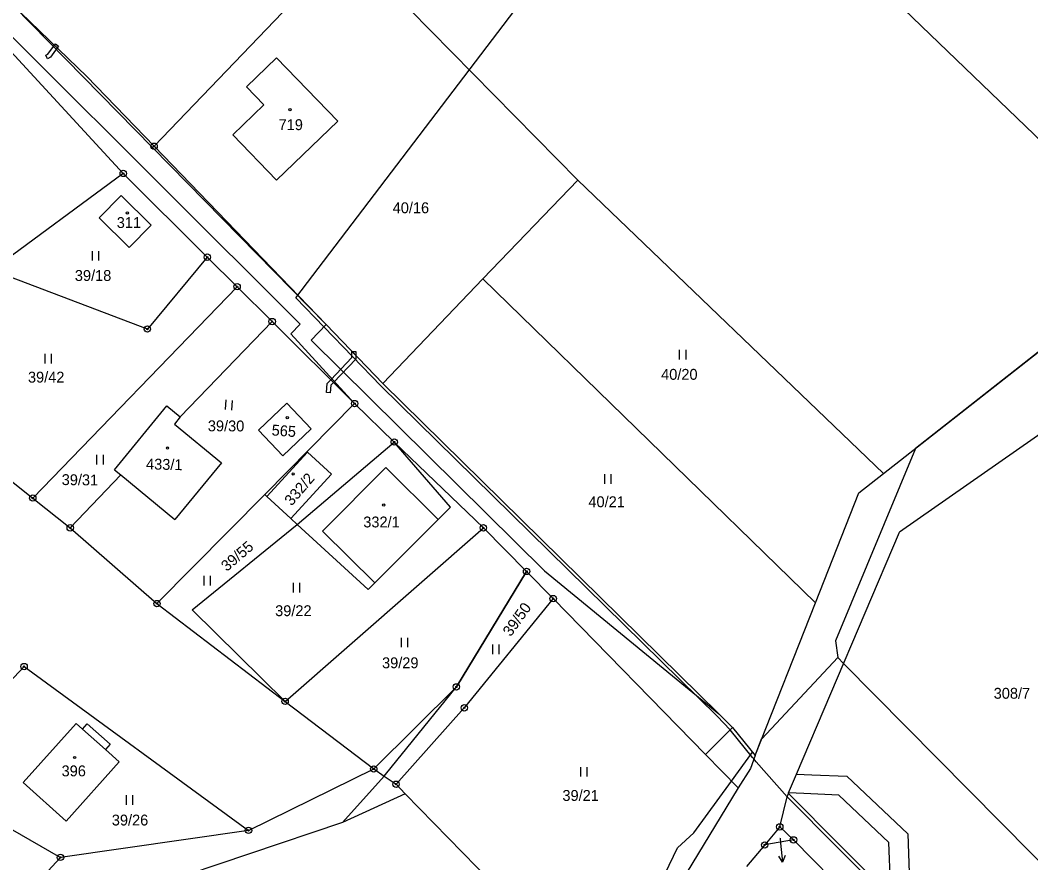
# Model space of a CAD drawing. Extents: x -445050 to -440454, y -1134563 to -1129741.
# Drawn here: x -442715.2 to -442557.4, y -1130802.1 to -1130670.5 of the extents above; entities that cross this region are included whole.
import ezdxf

# ---------------------------------------------------------------- set-up
doc = ezdxf.new("R2010")
doc.units = 0
for name, color, linetype in [('Vrstva 1', 7, 'Continuous'), ('Vrstva 16', 7, 'Continuous'), ('Vrstva 18', 7, 'Continuous'), ('Vrstva 19', 7, 'Continuous'), ('Vrstva 24', 7, 'Continuous'), ('Vrstva 25', 7, 'Continuous'), ('Vrstva 3', 7, 'Continuous'), ('Vrstva 30', 7, 'Continuous'), ('Vrstva 37', 7, 'Continuous'), ('Vrstva 4', 7, 'Continuous'), ('Vrstva 5', 7, 'Continuous'), ('Vrstva 52', 7, 'Continuous'), ('Vrstva 6', 7, 'Continuous')]:
    doc.layers.add(name, color=color, linetype=linetype)

msp = doc.modelspace()

# ---------------------------------------------------------------- linework, layer by layer
at = {"layer": 'Vrstva 1'}
for p, q in [((-442704.75, -1130679.31), (-442715.08, -1130669.35)), ((-442675.13, -1130676.37), (-442679.84, -1130680.93)), ((-442665.58, -1130686.25), (-442675.13, -1130676.37)), ((-442679.84, -1130680.93), (-442677.14, -1130683.73)), ((-442677.14, -1130683.73), (-442681.99, -1130688.4)), ((-442675.16, -1130695.49), (-442665.58, -1130686.25)), ((-442681.99, -1130688.4), (-442675.16, -1130695.49))]:
    msp.add_line(p, q, dxfattribs=at)
for points in [[(-442664.18, -1130658.76), (-442694.26, -1130690.19)], [(-442664.18, -1130658.76), (-442628.11, -1130695.47)], [(-442719.7, -1130672.12), (-442699.07, -1130694.44)], [(-442704.75, -1130679.31), (-442694.26, -1130690.19)], [(-442694.26, -1130690.19), (-442667.41, -1130718.05)], [(-442699.07, -1130694.44), (-442719.59, -1130709.52)], [(-442685.95, -1130707.52), (-442699.07, -1130694.44)], [(-442642.91, -1130710.91), (-442628.11, -1130695.47)], [(-442702.84, -1130701.37), (-442699.4, -1130697.88)], [(-442699.4, -1130697.88), (-442694.7, -1130702.52)], [(-442698.15, -1130706), (-442702.84, -1130701.37)], [(-442694.7, -1130702.52), (-442698.15, -1130706)], [(-442685.95, -1130707.52), (-442695.31, -1130718.74)], [(-442681.3, -1130712.13), (-442685.95, -1130707.52)], [(-442695.31, -1130718.74), (-442719.59, -1130709.52)], [(-442681.3, -1130712.13), (-442713.2, -1130745.14)], [(-442681.3, -1130712.13), (-442675.83, -1130717.57)], [(-442658.56, -1130727.23), (-442642.91, -1130710.91)], [(-442675.83, -1130717.57), (-442690.17, -1130732.48)], [(-442675.83, -1130717.57), (-442662.95, -1130730.38)], [(-442667.41, -1130718.05), (-442658.56, -1130727.23)], [(-442580.36, -1130741.3), (-442555.52, -1130721.77)], [(-442658.56, -1130727.23), (-442606.08, -1130778.83)], [(-442732.98, -1130729.42), (-442713.2, -1130745.14)], [(-442700.44, -1130740.73), (-442692.26, -1130730.76)], [(-442692.26, -1130730.76), (-442690.17, -1130732.48)], [(-442677.96, -1130734.56), (-442673.55, -1130730.34)], [(-442676.99, -1130744.59), (-442662.95, -1130730.38)], [(-442673.55, -1130730.34), (-442669.76, -1130734.32)], [(-442662.95, -1130730.38), (-442656.76, -1130736.39)], [(-442690.17, -1130732.48), (-442691.09, -1130733.59)], [(-442551.85, -1130732.3), (-442577.91, -1130750.47)], [(-442691.09, -1130733.59), (-442683.71, -1130739.65)], [(-442669.76, -1130734.32), (-442674.17, -1130738.54)], [(-442674.17, -1130738.54), (-442677.96, -1130734.56)], [(-442671.91, -1130749.25), (-442656.76, -1130736.39)], [(-442642.85, -1130749.79), (-442656.76, -1130736.39)], [(-442648, -1130746.55), (-442656.76, -1130736.39)], [(-442700.44, -1130740.73), (-442699.45, -1130741.54)], [(-442683.71, -1130739.65), (-442691.01, -1130748.48)], [(-442699.45, -1130741.54), (-442707.35, -1130749.79)], [(-442699.45, -1130741.54), (-442691.01, -1130748.48)], [(-442584.21, -1130744.32), (-442580.36, -1130741.3)], [(-442713.2, -1130745.14), (-442707.35, -1130749.79)], [(-442693.81, -1130761.63), (-442676.99, -1130744.59)], [(-442676.99, -1130744.59), (-442676.67, -1130744.88)], [(-442676.67, -1130744.88), (-442672.91, -1130748.33)], [(-442591, -1130761.49), (-442584.21, -1130744.32)], [(-442648, -1130746.55), (-442649.93, -1130748.49)], [(-442672.91, -1130748.33), (-442671.91, -1130749.25)], [(-442649.93, -1130748.49), (-442659.81, -1130758.41)], [(-442707.35, -1130749.79), (-442693.81, -1130761.63)], [(-442688.33, -1130762.58), (-442671.91, -1130749.25)], [(-442673.81, -1130776.9), (-442642.85, -1130749.79)], [(-442671.91, -1130749.25), (-442660.83, -1130759.44)], [(-442642.85, -1130749.79), (-442636.1, -1130756.6)], [(-442593.94, -1130788.25), (-442577.91, -1130750.47)], [(-442636.1, -1130756.6), (-442647.07, -1130774.64)], [(-442636.1, -1130756.6), (-442631.95, -1130760.85)], [(-442659.81, -1130758.41), (-442660.83, -1130759.44)], [(-442631.95, -1130760.85), (-442645.83, -1130777.91)], [(-442631.95, -1130760.85), (-442608.19, -1130785.18)], [(-442693.81, -1130761.63), (-442673.81, -1130776.9)], [(-442688.33, -1130762.58), (-442673.81, -1130776.9)], [(-442600.44, -1130785.36), (-442591, -1130761.49)], [(-442714.55, -1130771.46), (-442730.78, -1130788.7)], [(-442714.55, -1130771.46), (-442679.52, -1130797.05)], [(-442659.97, -1130787.46), (-442647.07, -1130774.64)], [(-442673.81, -1130776.9), (-442659.97, -1130787.46)], [(-442645.83, -1130777.91), (-442656.49, -1130789.84)], [(-442606.08, -1130778.83), (-442603.98, -1130780.97)], [(-442714.68, -1130789.58), (-442706.4, -1130780.35)], [(-442706.4, -1130780.35), (-442705.43, -1130781.22)], [(-442705.43, -1130781.22), (-442704.7, -1130780.4)], [(-442704.7, -1130780.4), (-442701.12, -1130783.6)], [(-442603.98, -1130780.97), (-442600.44, -1130785.36)], [(-442701.12, -1130783.6), (-442701.86, -1130784.42)], [(-442701.86, -1130784.42), (-442699.7, -1130786.36)], [(-442699.7, -1130786.36), (-442707.98, -1130795.59)], [(-442608.19, -1130785.18), (-442603.08, -1130790.41)], [(-442600.44, -1130785.36), (-442601.15, -1130787.39)], [(-442679.52, -1130797.05), (-442659.97, -1130787.46)], [(-442659.97, -1130787.46), (-442658.35, -1130788.57)], [(-442601.15, -1130787.39), (-442603.08, -1130790.41)], [(-442730.78, -1130788.7), (-442708.87, -1130801.27)], [(-442707.98, -1130795.59), (-442714.68, -1130789.58)], [(-442658.35, -1130788.57), (-442656.49, -1130789.84)], [(-442595.19, -1130791.2), (-442593.94, -1130788.25)], [(-442656.49, -1130789.84), (-442655.04, -1130791.32)], [(-442603.08, -1130790.41), (-442621.06, -1130820.09)], [(-442595.24, -1130791.31), (-442595.19, -1130791.2)], [(-442655.04, -1130791.32), (-442664.85, -1130795.84)], [(-442655.04, -1130791.32), (-442628.23, -1130818.86)], [(-442596.58, -1130796.51), (-442595.44, -1130791.82)], [(-442595.44, -1130791.82), (-442595.24, -1130791.31)], [(-442595.24, -1130791.31), (-442579.23, -1130807.39)], [(-442664.85, -1130795.84), (-442708.39, -1130810.49)], [(-442679.52, -1130797.05), (-442708.87, -1130801.27)], [(-442596.58, -1130796.51), (-442598.93, -1130799.33)], [(-442596.58, -1130796.51), (-442594.43, -1130798.54)], [(-442594.43, -1130798.54), (-442598.93, -1130799.33)], [(-442594.43, -1130798.54), (-442567.43, -1130826.02)], [(-442598.93, -1130799.33), (-442601.75, -1130802.71)], [(-442713.44, -1130806.24), (-442708.87, -1130801.27)]]:
    msp.add_lwpolyline(points, dxfattribs=at)
at = {"layer": 'Vrstva 16'}
msp.add_line((-442596.45, -1130799.04), (-442596.13, -1130802.02), dxfattribs=at)
for points in [[(-442596.53, -1130798.29), (-442596.45, -1130799.04)], [(-442595.74, -1130800.97), (-442596.13, -1130802.02), (-442596.73, -1130801.08)]]:
    msp.add_lwpolyline(points, dxfattribs=at)
at = {"layer": 'Vrstva 24'}
for centre, radius in [((-442694.26, -1130690.19), 0.5), ((-442694.26, -1130690.19), 0.1), ((-442699.07, -1130694.44), 0.5), ((-442699.07, -1130694.44), 0.1), ((-442685.95, -1130707.52), 0.5), ((-442685.95, -1130707.52), 0.1), ((-442681.3, -1130712.13), 0.5), ((-442681.3, -1130712.13), 0.1), ((-442675.83, -1130717.57), 0.5), ((-442695.31, -1130718.74), 0.5), ((-442695.31, -1130718.74), 0.1), ((-442675.83, -1130717.57), 0.1), ((-442662.95, -1130730.38), 0.5), ((-442662.95, -1130730.38), 0.1), ((-442656.76, -1130736.39), 0.5), ((-442656.76, -1130736.39), 0.1), ((-442713.2, -1130745.14), 0.5), ((-442713.2, -1130745.14), 0.1), ((-442707.35, -1130749.79), 0.5), ((-442707.35, -1130749.79), 0.1), ((-442642.85, -1130749.79), 0.5), ((-442642.85, -1130749.79), 0.1), ((-442636.1, -1130756.6), 0.5), ((-442636.1, -1130756.6), 0.1), ((-442693.81, -1130761.63), 0.5), ((-442631.95, -1130760.85), 0.5), ((-442631.95, -1130760.85), 0.1), ((-442693.81, -1130761.63), 0.1), ((-442714.55, -1130771.46), 0.5), ((-442714.55, -1130771.46), 0.1), ((-442647.07, -1130774.64), 0.5), ((-442647.07, -1130774.64), 0.1), ((-442673.81, -1130776.9), 0.5), ((-442673.81, -1130776.9), 0.1), ((-442645.83, -1130777.91), 0.5), ((-442645.83, -1130777.91), 0.1), ((-442659.97, -1130787.46), 0.5), ((-442659.97, -1130787.46), 0.1), ((-442656.49, -1130789.84), 0.5), ((-442656.49, -1130789.84), 0.1), ((-442679.52, -1130797.05), 0.5), ((-442679.52, -1130797.05), 0.1), ((-442596.58, -1130796.51), 0.5), ((-442596.58, -1130796.51), 0.1), ((-442598.93, -1130799.33), 0.5), ((-442594.43, -1130798.54), 0.5), ((-442594.43, -1130798.54), 0.1), ((-442598.93, -1130799.33), 0.1), ((-442708.87, -1130801.27), 0.5), ((-442708.87, -1130801.27), 0.1)]:
    msp.add_circle(centre, radius, dxfattribs=at)
at = {"layer": 'Vrstva 25'}
for p, q in [((-442703.89, -1130708.06), (-442703.89, -1130706.56)), ((-442702.89, -1130708.06), (-442702.89, -1130706.56)), ((-442711.26, -1130724.13), (-442711.26, -1130722.63)), ((-442710.26, -1130724.13), (-442710.26, -1130722.63)), ((-442612.21, -1130723.51), (-442612.21, -1130722.01)), ((-442611.21, -1130723.51), (-442611.21, -1130722.01)), ((-442683.12, -1130731.31), (-442683.01, -1130729.82)), ((-442682.12, -1130731.39), (-442682.01, -1130729.89)), ((-442703.18, -1130739.88), (-442703.18, -1130738.38)), ((-442702.18, -1130739.88), (-442702.18, -1130738.38)), ((-442623.9, -1130742.9), (-442623.9, -1130741.4)), ((-442622.9, -1130742.9), (-442622.9, -1130741.4)), ((-442686.46, -1130758.78), (-442686.46, -1130757.28)), ((-442685.46, -1130758.78), (-442685.46, -1130757.28)), ((-442672.48, -1130759.91), (-442672.48, -1130758.41)), ((-442671.48, -1130759.91), (-442671.48, -1130758.41)), ((-442655.62, -1130768.45), (-442655.62, -1130766.95)), ((-442654.62, -1130768.45), (-442654.62, -1130766.95)), ((-442641.37, -1130769.53), (-442641.37, -1130768.03)), ((-442640.37, -1130769.53), (-442640.37, -1130768.03)), ((-442627.64, -1130788.66), (-442627.64, -1130787.16)), ((-442626.64, -1130788.66), (-442626.64, -1130787.16)), ((-442698.59, -1130793.05), (-442698.59, -1130791.55)), ((-442697.59, -1130793.05), (-442697.59, -1130791.55))]:
    msp.add_line(p, q, dxfattribs=at)
for centre in [(-442673.05, -1130684.47), (-442698.43, -1130700.6), (-442673.46, -1130732.59), (-442692.17, -1130737.34), (-442672.54, -1130741.38), (-442658.41, -1130746.23), (-442706.66, -1130785.67)]:
    msp.add_circle(centre, 0.175, dxfattribs=at)
at = {"layer": 'Vrstva 3'}
for points in [[(-442675.13, -1130676.37), (-442679.84, -1130680.93)], [(-442665.58, -1130686.25), (-442675.13, -1130676.37)], [(-442679.84, -1130680.93), (-442677.14, -1130683.73)], [(-442677.14, -1130683.73), (-442681.99, -1130688.4)], [(-442675.16, -1130695.49), (-442665.58, -1130686.25)], [(-442681.99, -1130688.4), (-442675.16, -1130695.49)], [(-442702.84, -1130701.37), (-442699.4, -1130697.88)], [(-442699.4, -1130697.88), (-442694.7, -1130702.52)], [(-442698.15, -1130706), (-442702.84, -1130701.37)], [(-442694.7, -1130702.52), (-442698.15, -1130706)], [(-442700.44, -1130740.73), (-442692.26, -1130730.76)], [(-442692.26, -1130730.76), (-442690.17, -1130732.48)], [(-442677.96, -1130734.56), (-442673.55, -1130730.34)], [(-442673.55, -1130730.34), (-442669.76, -1130734.32)], [(-442690.17, -1130732.48), (-442691.09, -1130733.59)], [(-442691.09, -1130733.59), (-442683.71, -1130739.65)], [(-442669.76, -1130734.32), (-442674.17, -1130738.54)], [(-442674.17, -1130738.54), (-442677.96, -1130734.56)], [(-442670.32, -1130737.96), (-442676.67, -1130744.88)], [(-442666.56, -1130741.41), (-442670.32, -1130737.96)], [(-442700.44, -1130740.73), (-442699.45, -1130741.54)], [(-442683.71, -1130739.65), (-442691.01, -1130748.48)], [(-442667.96, -1130750.29), (-442658.08, -1130740.37)], [(-442658.08, -1130740.37), (-442649.93, -1130748.49)], [(-442699.45, -1130741.54), (-442691.01, -1130748.48)], [(-442672.91, -1130748.33), (-442666.56, -1130741.41)], [(-442676.67, -1130744.88), (-442672.91, -1130748.33)], [(-442649.93, -1130748.49), (-442659.81, -1130758.41)], [(-442659.81, -1130758.41), (-442667.96, -1130750.29)], [(-442714.68, -1130789.58), (-442706.4, -1130780.35)], [(-442706.4, -1130780.35), (-442705.43, -1130781.22)], [(-442705.43, -1130781.22), (-442701.86, -1130784.42)], [(-442701.86, -1130784.42), (-442699.7, -1130786.36)], [(-442699.7, -1130786.36), (-442707.98, -1130795.59)], [(-442707.98, -1130795.59), (-442714.68, -1130789.58)]]:
    msp.add_lwpolyline(points, dxfattribs=at)
at = {"layer": 'Vrstva 30'}
for points in [[(-442735.26, -1130652.59), (-442716.14, -1130668.32), (-442667.41, -1130718.05), (-442669.73, -1130720.49), (-442633.32, -1130756.52), (-442606.08, -1130778.83), (-442603.98, -1130780.97), (-442608.19, -1130785.18), (-442631.95, -1130760.85), (-442645.83, -1130777.91), (-442656.49, -1130789.84), (-442655.04, -1130791.32), (-442664.85, -1130795.84), (-442658.35, -1130788.57), (-442658.14, -1130788.34), (-442647.07, -1130774.64), (-442636.1, -1130756.6), (-442642.85, -1130749.79), (-442656.76, -1130736.39), (-442662.95, -1130730.38), (-442672.92, -1130719.48), (-442671.46, -1130717.96), (-442736.07, -1130653.46), (-442735.26, -1130652.59)], [(-442709.82, -1130674.42), (-442709.39, -1130674.84), (-442710.43, -1130676.29), (-442710.89, -1130676.51), (-442711.15, -1130675.97), (-442710.83, -1130675.81), (-442709.82, -1130674.42)], [(-442709.82, -1130674.42), (-442709.66, -1130674.19), (-442709.18, -1130674.55), (-442709.39, -1130674.84), (-442709.82, -1130674.42)], [(-442666.68, -1130726.68), (-442663.38, -1130723.21), (-442663.38, -1130722.24), (-442662.78, -1130722.85), (-442662.78, -1130723.45), (-442666.25, -1130727.1), (-442666.68, -1130726.68)], [(-442662.78, -1130722.23), (-442662.78, -1130722.85), (-442663.38, -1130722.24), (-442662.78, -1130722.23)], [(-442666.76, -1130728.71), (-442667.36, -1130728.65), (-442667.24, -1130727.27), (-442666.68, -1130726.68), (-442666.25, -1130727.1), (-442666.66, -1130727.53), (-442666.76, -1130728.71)], [(-442595.19, -1130791.2), (-442593.94, -1130788.25), (-442591.57, -1130788.35), (-442586.13, -1130788.58), (-442576.57, -1130797.6), (-442576.3, -1130805.27), (-442576.12, -1130810.52), (-442579.23, -1130807.39), (-442579.3, -1130805.38), (-442579.53, -1130798.94), (-442587.37, -1130791.53), (-442592.81, -1130791.3), (-442595.19, -1130791.2)]]:
    msp.add_lwpolyline(points, dxfattribs=at)
at = {"layer": 'Vrstva 37'}
for centre in [(-442673.05, -1130684.47), (-442698.43, -1130700.6), (-442673.46, -1130732.59), (-442692.17, -1130737.34), (-442672.54, -1130741.38), (-442658.41, -1130746.23), (-442706.66, -1130785.67)]:
    msp.add_circle(centre, 0.175, dxfattribs=at)
at = {"layer": 'Vrstva 4'}
for points in [[(-442670.32, -1130737.96), (-442676.67, -1130744.88)], [(-442666.56, -1130741.41), (-442670.32, -1130737.96)], [(-442667.96, -1130750.29), (-442658.08, -1130740.37)], [(-442658.08, -1130740.37), (-442649.93, -1130748.49)], [(-442672.91, -1130748.33), (-442666.56, -1130741.41)], [(-442659.81, -1130758.41), (-442667.96, -1130750.29)], [(-442705.43, -1130781.22), (-442701.86, -1130784.42)]]:
    msp.add_lwpolyline(points, dxfattribs=at)
at = {"layer": 'Vrstva 5'}
for points in [[(-442672.12, -1130713.86), (-442551.14, -1130554.82)], [(-442672.12, -1130713.86), (-442658.85, -1130727.63)], [(-442606.37, -1130779.23), (-442658.85, -1130727.63)], [(-442604.34, -1130781.33), (-442606.37, -1130779.23)], [(-442600.83, -1130785.67), (-442604.34, -1130781.33)], [(-442600.63, -1130785.9), (-442600.83, -1130785.67)], [(-442600.25, -1130786.33), (-442600.63, -1130785.9)], [(-442595.44, -1130791.82), (-442600.25, -1130786.33)], [(-442579.58, -1130807.74), (-442595.44, -1130791.82)]]:
    msp.add_lwpolyline(points, dxfattribs=at)
at = {"layer": 'Vrstva 52'}
for points in [[(-442551.46, -1130554.43), (-442549.35, -1130557), (-442548.67, -1130556.55), (-442520.3, -1130583.3), (-442524.35, -1130587.57), (-442518.74, -1130594.43), (-442495.48, -1130622.9), (-442490.57, -1130628.93), (-442502.12, -1130676.66), (-442503.17, -1130679.42), (-442511.68, -1130701.43), (-442507.95, -1130706.02), (-442509.44, -1130708.14), (-442514.35, -1130708.33), (-442520.25, -1130723.59), (-442555.52, -1130721.77), (-442575.4, -1130737.4), (-442587.88, -1130767.45), (-442587.51, -1130770.05)], [(-442587.51, -1130770.05), (-442586.61, -1130770.97), (-442547.44, -1130810.59), (-442529.69, -1130828.54), (-442523.11, -1130835.19), (-442522.62, -1130835.69), (-442514.1, -1130844.99), (-442510.71, -1130848.68), (-442503.91, -1130856.1), (-442502.42, -1130856.1), (-442500, -1130856.11), (-442494.33, -1130847.75), (-442475.2, -1130806.93), (-442474.67, -1130804.47), (-442467.97, -1130772.92), (-442467.94, -1130772.85), (-442465.63, -1130767.81), (-442457.12, -1130742.3), (-442447.89, -1130720.58), (-442435.09, -1130688.21), (-442433.7, -1130672.39)], [(-442652.51, -1130871.19), (-442650.19, -1130863.93), (-442647.62, -1130855.89), (-442647.62, -1130853.12), (-442644.92, -1130847.5), (-442641.9, -1130841.23), (-442636.99, -1130831.02), (-442633.36, -1130825.87), (-442630.4, -1130821.66), (-442627.94, -1130818.91), (-442614.45, -1130803.81), (-442612.54, -1130799.77), (-442609.99, -1130797.43), (-442604.13, -1130789.34), (-442600.86, -1130784.83), (-442600.44, -1130785.36), (-442599.47, -1130782.92), (-442599.36, -1130782.76), (-442587.51, -1130770.05)]]:
    msp.add_lwpolyline(points, dxfattribs=at)
at = {"layer": 'Vrstva 6'}
for points in [[(-442520.25, -1130723.59), (-442735.95, -1130516.07)], [(-442628.11, -1130695.47), (-442580.36, -1130741.3)], [(-442642.91, -1130710.91), (-442591, -1130761.49)]]:
    msp.add_lwpolyline(points, dxfattribs=at)

# ---------------------------------------------------------------- texts
at = {"layer": 'Vrstva 18'}
for s, height, p in [('40/16', 1.7, (-442657.01, -1130700.65)), ('39/18', 1.7, (-442706.63, -1130711.23)), ('40/20', 1.7, (-442615.1, -1130726.67)), ('39/42', 1.7, (-442713.95, -1130727.11)), ('40/21', 1.7, (-442626.45, -1130746.57)), ('39/22', 1.7, (-442675.36, -1130763.59)), ('39/29', 1.7, (-442658.67, -1130771.73)), ('308/7', 1.7, (-442563.18, -1130776.49)), ('39/21', 1.7, (-442630.51, -1130792.45)), ('39/26', 1.7, (-442700.86, -1130796.29)), ('2049', 0.1, (-442596.68, -1130798.29))]:
    msp.add_text(s, height=height, dxfattribs=at).set_placement(p)
for s, rotation, p in [('39/30', 359.7565, (-442685.87, -1130734.71)), ('39/31', 359.36, (-442708.69, -1130743.11)), ('39/55', 40.5027, (-442682.9, -1130756.69)), ('39/50', 54.5445, (-442638.58, -1130766.89))]:
    msp.add_text(s, height=1.7, rotation=rotation, dxfattribs=at).set_placement(p)
at = {"layer": 'Vrstva 19'}
for s, p in [('719', (-442674.82, -1130687.67)), ('311', (-442700.09, -1130702.96)), ('332/1', (-442661.6, -1130749.73)), ('396', (-442708.7, -1130788.61))]:
    msp.add_text(s, height=1.7, dxfattribs=at).set_placement(p)
for s, rotation, p in [('565', 355.8987, (-442675.95, -1130735.35)), ('433/1', 358.6415, (-442695.53, -1130740.66)), ('332/2', 49.5504, (-442672.78, -1130746.47))]:
    msp.add_text(s, height=1.7, rotation=rotation, dxfattribs=at).set_placement(p)

doc.saveas('drawing.dxf')
